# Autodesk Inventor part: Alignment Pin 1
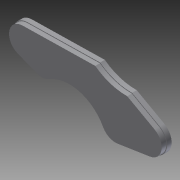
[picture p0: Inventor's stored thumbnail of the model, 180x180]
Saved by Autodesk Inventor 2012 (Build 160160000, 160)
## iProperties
Created: 2013-01
Part Number: Alignment Pin 1
Material: Default
Document SubType Name: Modeling
Designer: Alex
Density: 1 g/cm^3
Mass: 0.0633152 g
Surface Area: 1.67374 cm^2
Volume: 0.0633152 cm^3
Author: Alex
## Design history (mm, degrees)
sketch "Sketch1"
  geometry: L1 (-21.6, 1.097)-(-18.06, 1.64); L2 (-32.501, 4.156)-(-30.415, 3.347); A1 r 1.587 centre (-21.841, 2.666) between (-23.242, 1.92) and (-21.6, 1.097); A2 r 1.588 centre (-18.29, 3.211) between (-18.06, 1.64) and (-17.534, 4.607); A3 r 1.587 centre (-22.97, 5.81) between (-22.399, 7.291) and (-23, 7.397); A4 r 5.652 centre (-20.62, 11.906) between (-24.002, 7.378) and (-20.519, 6.255); A5 r 4.089 centre (-26.853, 0) between (-23.242, 1.92) and (-29.005, 3.477); A6 r 1.588 centre (-29.841, 4.827) between (-30.415, 3.347) and (-29.005, 3.477); A7 r 1.587 centre (-31.928, 5.637) between (-31.956, 7.224) and (-32.501, 4.156); 2 other entities
  constraints: 14 point on circle, 7 centre point, 4 end point, 6 other
extrude "Extrusion3" new body sketch "Sketch1" distance "d51" = 1.016; taper "d52" = 0 deg
sketch "Sketch3"
  geometry: L1 (-21.6, 1.097)-(-18.06, 1.64) reference; L2 (-17.534, 4.607)-(-20.519, 6.255) reference; L3 (-24.002, 7.378)-(-31.956, 7.224) reference; L4 (-32.501, 4.156)-(-30.415, 3.347) reference; L5 (-31.958, 7.148)-(-24.027, 7.301); L6 (-20.538, 6.178)-(-17.57, 4.54); L7 (-18.071, 1.715)-(-21.611, 1.172); L8 (-30.387, 3.418)-(-32.475, 4.228); A1 r 1.588 centre (-18.29, 3.211) between (-18.06, 1.64) and (-17.534, 4.607) reference; A2 r 5.652 centre (-20.62, 11.906) between (-24.002, 7.378) and (-20.519, 6.255) reference; A3 r 1.587 centre (-31.928, 5.637) between (-31.956, 7.224) and (-32.501, 4.156) reference; A4 r 1.588 centre (-29.841, 4.827) between (-30.415, 3.347) and (-29.005, 3.477) reference; A5 r 4.089 centre (-26.853, 0) between (-23.242, 1.92) and (-29.005, 3.477) reference; A6 r 1.587 centre (-21.841, 2.666) between (-23.242, 1.92) and (-21.6, 1.097) reference; A7 r 5.728 centre (-20.62, 11.906) between (-24.027, 7.301) and (-20.538, 6.178); A8 r 1.511 centre (-18.29, 3.211) between (-18.071, 1.715) and (-17.57, 4.54); A9 r 1.511 centre (-21.841, 2.666) between (-23.175, 1.956) and (-21.611, 1.172); A10 r 4.166 centre (-26.853, 0) between (-23.175, 1.956) and (-29.045, 3.542); A11 r 1.511 centre (-29.841, 4.827) between (-30.387, 3.418) and (-29.045, 3.542); A12 r 1.511 centre (-31.928, 5.637) between (-31.958, 7.148) and (-32.475, 4.228); 1 further point
  constraints: 12 point on circle, 8 end point, 6 centre point, 9 other
  dimensions: "d53" = 0.0762 distance between parallel lines of L3 L5
extrude "Extrusion4" cut sketch "Sketch3" distance "d54" = 0.508; taper "d55" = 0 deg
body "Solid2"
